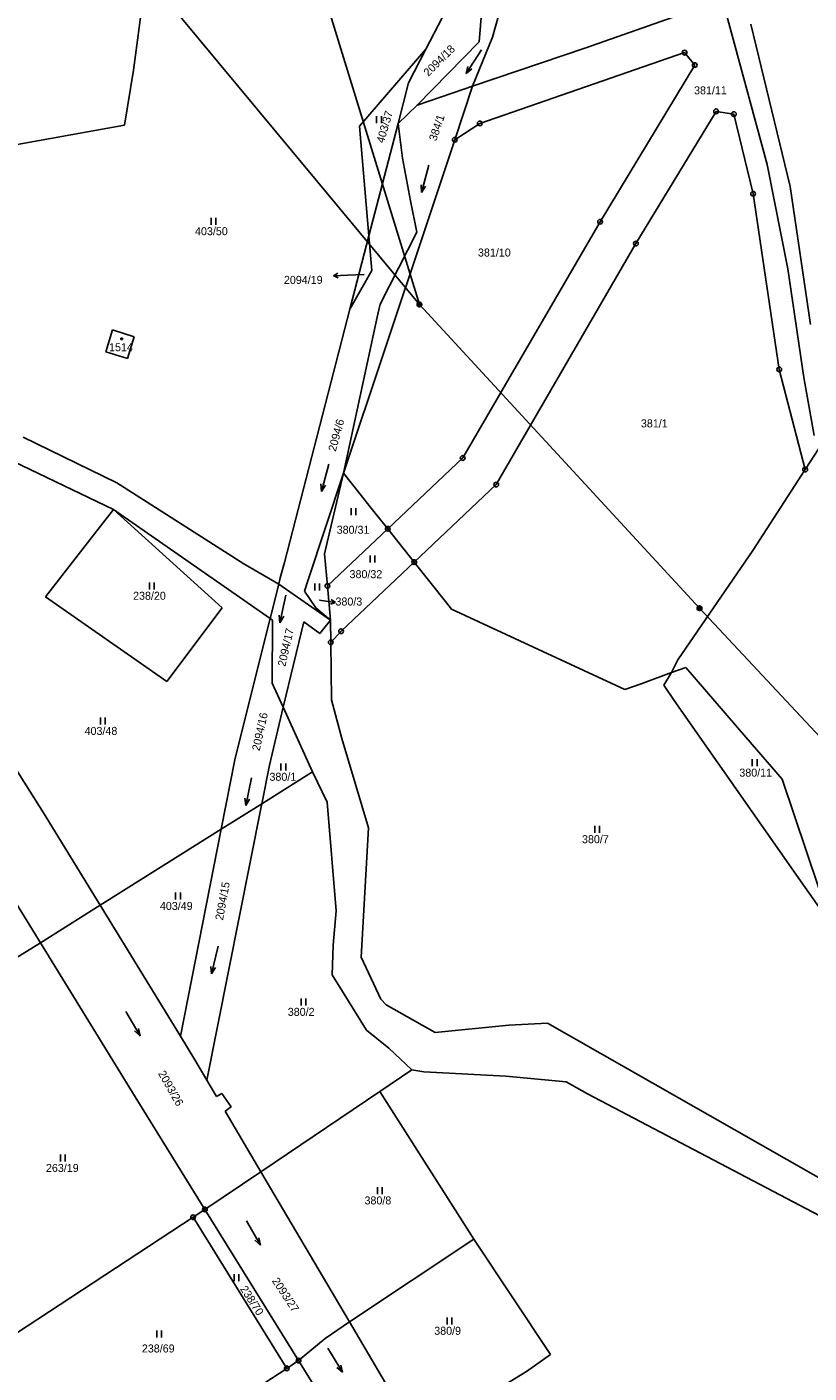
# Model space of a CAD drawing. Extents: x -795483 to -789093, y -1112258 to -1108741.
# Drawn here: x -791422.1 to -791256, y -1111421 to -1111135 of the extents above; entities that cross this region are included whole.
import ezdxf

# ---------------------------------------------------------------- set-up
doc = ezdxf.new("R2010")
doc.units = 0
for name, color, linetype in [('Komunikace', 7, 'Continuous'), ('Vrstva 1', 7, 'Continuous'), ('Vrstva 12', 7, 'Continuous'), ('Vrstva 14', 7, 'Continuous'), ('Vrstva 15', 7, 'Continuous'), ('Vrstva 16', 7, 'Continuous'), ('Vrstva 23', 7, 'Continuous'), ('Vrstva 25', 7, 'Continuous'), ('Vrstva 26', 7, 'Continuous'), ('Vrstva 28', 7, 'Continuous')]:
    doc.layers.add(name, color=color, linetype=linetype)

msp = doc.modelspace()

# ---------------------------------------------------------------- linework, layer by layer
at = {"layer": 'Komunikace'}
for p, q in [((-791350.48, -1111187.58), (-791354.05, -1111187.75)), ((-791359.99, -1111256.79), (-791359.58, -1111256.85))]:
    msp.add_line(p, q, dxfattribs=at)
at = {"layer": 'Vrstva 1'}
for p, q in [((-791326.07, -1111138.17), (-791324.04, -1111113.88)), ((-791399.5, -1111144.17), (-791397.48, -1111128.65)), ((-791303.42, -1111139.47), (-791274.38, -1111129.16)), ((-791274.38, -1111129.16), (-791264.93, -1111164.26)), ((-791321.94, -1111132.66), (-791323.21, -1111137.18)), ((-791333.93, -1111133.04), (-791337.37, -1111139.71)), ((-791268.4, -1111134.43), (-791260.02, -1111168.91)), ((-791326.07, -1111138.17), (-791339.22, -1111151.65)), ((-791323.21, -1111137.18), (-791327.47, -1111147.59)), ((-791351.47, -1111156.08), (-791337.37, -1111139.71)), ((-791337.37, -1111139.71), (-791341.07, -1111146.89)), ((-791327.47, -1111147.59), (-791303.42, -1111139.47)), ((-791325.94, -1111155.52), (-791282.44, -1111140.47)), ((-791282.44, -1111140.47), (-791280.29, -1111143.11)), ((-791401.41, -1111155.85), (-791399.5, -1111144.17)), ((-791280.29, -1111143.11), (-791300.38, -1111176.39)), ((-791341.07, -1111146.89), (-791343.31, -1111155.52)), ((-791329.35, -1111148.24), (-791339.22, -1111151.65)), ((-791327.47, -1111147.59), (-791331.26, -1111158.97)), ((-791327.47, -1111147.59), (-791329.35, -1111148.24)), ((-791339.22, -1111151.65), (-791343.31, -1111155.52)), ((-791343.31, -1111155.52), (-791349.49, -1111179.38)), ((-791342.38, -1111162.91), (-791343.31, -1111155.52)), ((-791331.26, -1111158.97), (-791325.94, -1111155.52)), ((-791292.78, -1111181.02), (-791275.74, -1111152.94)), ((-791275.74, -1111152.94), (-791271.97, -1111153.53)), ((-791271.97, -1111153.53), (-791267.88, -1111170.44)), ((-791448.95, -1111164.42), (-791401.41, -1111155.85)), ((-791349.49, -1111179.38), (-791351.47, -1111156.08)), ((-791337.36, -1111177.27), (-791331.26, -1111158.97)), ((-791340.69, -1111171.93), (-791342.38, -1111162.91)), ((-791264.93, -1111164.26), (-791260.5, -1111186.38)), ((-791260.02, -1111168.91), (-791255.67, -1111198.2)), ((-791339.35, -1111178.63), (-791340.69, -1111171.93)), ((-791267.88, -1111170.44), (-791262.33, -1111207.77)), ((-791337.36, -1111177.27), (-791354.86, -1111229.83)), ((-791300.38, -1111176.39), (-791329.58, -1111226.58)), ((-791349.49, -1111179.38), (-791353.53, -1111194.98)), ((-791348.86, -1111186.78), (-791349.49, -1111179.38)), ((-791339.35, -1111178.63), (-791347.11, -1111193.89)), ((-791322.44, -1111232.22), (-791292.78, -1111181.02)), ((-791353.53, -1111194.98), (-791348.86, -1111186.78)), ((-791260.5, -1111186.38), (-791257.08, -1111209.51)), ((-791353.53, -1111194.98), (-791367.46, -1111248.75)), ((-791347.71, -1111196.68), (-791347.11, -1111193.89)), ((-791354.86, -1111229.83), (-791347.71, -1111196.68)), ((-791405.4, -1111204.02), (-791403.94, -1111199.37)), ((-791403.94, -1111199.37), (-791399.34, -1111200.82)), ((-791399.34, -1111200.82), (-791400.81, -1111205.47)), ((-791400.81, -1111205.47), (-791405.4, -1111204.02)), ((-791262.33, -1111207.77), (-791256.83, -1111229.05)), ((-791257.08, -1111209.51), (-791254.89, -1111221.77)), ((-791422.96, -1111222.17), (-791403.02, -1111231.88)), ((-791429.62, -1111225.1), (-791403.76, -1111237.54)), ((-791329.58, -1111226.58), (-791345.49, -1111241.62)), ((-791253.93, -1111224.59), (-791256.83, -1111229.05)), ((-791362.47, -1111252.68), (-791354.86, -1111229.83)), ((-791358.92, -1111246.95), (-791354.86, -1111229.83)), ((-791354.86, -1111229.83), (-791351.62, -1111233.9)), ((-791267.97, -1111246.2), (-791256.83, -1111229.05)), ((-791403.02, -1111231.88), (-791376.07, -1111249.07)), ((-791339.87, -1111248.69), (-791322.44, -1111232.22)), ((-791348.7, -1111237.57), (-791351.62, -1111233.9)), ((-791403.76, -1111237.54), (-791408.28, -1111243.34)), ((-791380.66, -1111258.43), (-791403.76, -1111237.54)), ((-791403.76, -1111237.54), (-791370.48, -1111260.67)), ((-791348.7, -1111237.57), (-791345.49, -1111241.62)), ((-791408.28, -1111243.34), (-791418.17, -1111256.04)), ((-791345.49, -1111241.62), (-791358.32, -1111253.75)), ((-791345.49, -1111241.62), (-791339.87, -1111248.69)), ((-791453.88, -1111246.33), (-791418.6, -1111301.97)), ((-791358.92, -1111246.95), (-791358.32, -1111253.75)), ((-791267.97, -1111246.2), (-791283.86, -1111269.47)), ((-791376.07, -1111249.07), (-791368.65, -1111253.35)), ((-791368.32, -1111252.05), (-791367.46, -1111248.75)), ((-791355.42, -1111263.38), (-791339.87, -1111248.69)), ((-791333.22, -1111257.08), (-791339.87, -1111248.69)), ((-791368.65, -1111253.35), (-791368.32, -1111252.05)), ((-791363.2, -1111254.85), (-791362.47, -1111252.68)), ((-791370.48, -1111260.67), (-791368.65, -1111253.35)), ((-791368.65, -1111253.35), (-791357.67, -1111261.03)), ((-791360.8, -1111258.43), (-791363.2, -1111254.85)), ((-791357.67, -1111261.03), (-791358.32, -1111253.75)), ((-791418.17, -1111256.04), (-791392.39, -1111274.08)), ((-791392.39, -1111274.08), (-791380.66, -1111258.43)), ((-791357.67, -1111261.03), (-791360.8, -1111258.43)), ((-791331.93, -1111258.71), (-791333.22, -1111257.08)), ((-791375.78, -1111281.83), (-791370.48, -1111260.67)), ((-791370.48, -1111260.67), (-791369.94, -1111261.05)), ((-791370.02, -1111274.39), (-791369.94, -1111261.05)), ((-791367.7, -1111279.54), (-791363.35, -1111261.36)), ((-791363.35, -1111261.36), (-791359.95, -1111263.88)), ((-791359.95, -1111263.88), (-791357.67, -1111261.03)), ((-791357.67, -1111261.03), (-791357.6, -1111265.74)), ((-791295.1, -1111275.79), (-791331.93, -1111258.71)), ((-791357.6, -1111265.74), (-791355.42, -1111263.38)), ((-791357.42, -1111277.96), (-791357.6, -1111265.74)), ((-791283.86, -1111269.47), (-791285.22, -1111272.18)), ((-791285.22, -1111272.18), (-791291.64, -1111274.53)), ((-791285.22, -1111272.18), (-791286.82, -1111274.87)), ((-791282.21, -1111271.08), (-791285.22, -1111272.18)), ((-791282.21, -1111271.08), (-791269.4, -1111285.92)), ((-791367.7, -1111279.54), (-791370.02, -1111274.39)), ((-791291.64, -1111274.53), (-791295.1, -1111275.79)), ((-791284.64, -1111278.11), (-791286.82, -1111274.87)), ((-791357.42, -1111277.96), (-791355.27, -1111286.17)), ((-791284.64, -1111278.11), (-791256.81, -1111317.81)), ((-791370.63, -1111291.8), (-791367.7, -1111279.54)), ((-791361.51, -1111293.27), (-791367.7, -1111279.54)), ((-791378, -1111290.71), (-791375.78, -1111281.83)), ((-791355.27, -1111286.17), (-791349.55, -1111305.18)), ((-791269.4, -1111285.92), (-791261.7, -1111294.84)), ((-791380.9, -1111305.45), (-791378, -1111290.71)), ((-791372.27, -1111300.03), (-791370.63, -1111291.8)), ((-791372.27, -1111300.03), (-791361.51, -1111293.27)), ((-791361.51, -1111293.27), (-791358.37, -1111299.69)), ((-791261.7, -1111294.84), (-791251.41, -1111325.54)), ((-791383.91, -1111358.78), (-791372.39, -1111300.65)), ((-791380.9, -1111305.45), (-791372.27, -1111300.03)), ((-791372.39, -1111300.65), (-791372.27, -1111300.03)), ((-791358.37, -1111299.69), (-791356.44, -1111322.75)), ((-791406.58, -1111321.6), (-791418.6, -1111301.97)), ((-791406.58, -1111321.6), (-791380.9, -1111305.45)), ((-791389.54, -1111349.43), (-791380.9, -1111305.45)), ((-791351.14, -1111332.63), (-791349.55, -1111305.18)), ((-791428.96, -1111313.82), (-791419.28, -1111329.58)), ((-791256.81, -1111317.81), (-791251.41, -1111325.54)), ((-791419.28, -1111329.58), (-791406.58, -1111321.6)), ((-791389.54, -1111349.43), (-791406.58, -1111321.6)), ((-791356.44, -1111322.75), (-791357.08, -1111330.07)), ((-791438.46, -1111341.46), (-791419.28, -1111329.58)), ((-791419.28, -1111329.58), (-791399.16, -1111362.32)), ((-791357.08, -1111330.07), (-791357.33, -1111336.34)), ((-791351.14, -1111332.63), (-791346.99, -1111341.56)), ((-791357.33, -1111336.34), (-791350.01, -1111348.13)), ((-791346.99, -1111341.56), (-791345.85, -1111342.74)), ((-791345.85, -1111342.74), (-791335.44, -1111348.6)), ((-791335.44, -1111348.6), (-791319.76, -1111347.09)), ((-791311.54, -1111346.61), (-791319.76, -1111347.09)), ((-791240.86, -1111386.95), (-791311.54, -1111346.61)), ((-791389.54, -1111349.43), (-791386.5, -1111354.4)), ((-791350.01, -1111348.13), (-791345.27, -1111351.93)), ((-791345.27, -1111351.93), (-791340.41, -1111356.55)), ((-791383.91, -1111358.78), (-791386.5, -1111354.4)), ((-791340.41, -1111356.55), (-791347.16, -1111361.17)), ((-791340.41, -1111356.55), (-791337.86, -1111356.95)), ((-791337.86, -1111356.95), (-791320.38, -1111357.9)), ((-791320.38, -1111357.9), (-791307.61, -1111359.07)), ((-791381.88, -1111362.23), (-791383.91, -1111358.78)), ((-791347.16, -1111361.17), (-791372.45, -1111378.21)), ((-791327.21, -1111392.51), (-791347.16, -1111361.17)), ((-791307.61, -1111359.07), (-791303.09, -1111361.64)), ((-791384.34, -1111386.22), (-791399.16, -1111362.32)), ((-791381.88, -1111362.23), (-791380.77, -1111361.55)), ((-791378.77, -1111364.41), (-791380.77, -1111361.55)), ((-791303.09, -1111361.64), (-791233.75, -1111398.07)), ((-791380.06, -1111365.31), (-791378.77, -1111364.41)), ((-791372.45, -1111378.21), (-791380.06, -1111365.31)), ((-791372.45, -1111378.21), (-791384.34, -1111386.22)), ((-791353.64, -1111410.08), (-791372.45, -1111378.21)), ((-791386.85, -1111387.87), (-791384.34, -1111386.22)), ((-791384.34, -1111386.22), (-791364.44, -1111418.33)), ((-791426.8, -1111414.15), (-791386.85, -1111387.87)), ((-791366.95, -1111419.97), (-791386.85, -1111387.87)), ((-791353.64, -1111410.08), (-791327.21, -1111392.51)), ((-791327.21, -1111392.51), (-791310.95, -1111417.05)), ((-791358.8, -1111413.62), (-791353.64, -1111410.08)), ((-791353.64, -1111410.08), (-791338.74, -1111435.33)), ((-791364.44, -1111418.33), (-791358.8, -1111413.62)), ((-791364.44, -1111418.33), (-791366.95, -1111419.97)), ((-791349.61, -1111442.25), (-791364.44, -1111418.33)), ((-791310.95, -1111417.05), (-791316.05, -1111420.64)), ((-791366.95, -1111419.97), (-791406.97, -1111446.05)), ((-791316.05, -1111420.64), (-791324.24, -1111425.65))]:
    msp.add_line(p, q, dxfattribs=at)
at = {"layer": 'Vrstva 12'}
for p, q in [((-791338.78, -1111193.96), (-791359.28, -1111127.18)), ((-791390.3, -1111131.95), (-791338.78, -1111193.96)), ((-791338.78, -1111193.96), (-791279.28, -1111258.5)), ((-791279.28, -1111258.5), (-791219.02, -1111322.91))]:
    msp.add_line(p, q, dxfattribs=at)
at = {"layer": 'Vrstva 16'}
for p, q in [((-791357.05, -1111187.89), (-791356.07, -1111187.34)), ((-791354.05, -1111187.75), (-791357.05, -1111187.89)), ((-791357.05, -1111187.89), (-791356.02, -1111188.34)), ((-791359.58, -1111256.85), (-791356.61, -1111257.27)), ((-791356.61, -1111257.27), (-791357.67, -1111257.62)), ((-791356.61, -1111257.27), (-791357.53, -1111256.63))]:
    msp.add_line(p, q, dxfattribs=at)
at = {"layer": 'Vrstva 23'}
for p, q in [((-791325.6, -1111139.87), (-791328.83, -1111144.93)), ((-791328.83, -1111144.93), (-791328.45, -1111143.4)), ((-791328.83, -1111144.93), (-791327.6, -1111143.93)), ((-791347.85, -1111155.46), (-791347.85, -1111153.96)), ((-791346.85, -1111153.96), (-791346.85, -1111155.46)), ((-791336.75, -1111164.37), (-791338.35, -1111170.15)), ((-791338.35, -1111170.15), (-791338.43, -1111168.57)), ((-791338.35, -1111170.15), (-791337.47, -1111168.84)), ((-791383.03, -1111177.05), (-791383.03, -1111175.55)), ((-791382.03, -1111175.55), (-791382.03, -1111177.05)), ((-791357.98, -1111227.89), (-791359.6, -1111233.67)), ((-791359.6, -1111233.67), (-791359.68, -1111232.09)), ((-791359.6, -1111233.67), (-791358.71, -1111232.36)), ((-791353.3, -1111238.76), (-791353.3, -1111237.26)), ((-791352.3, -1111237.26), (-791352.3, -1111238.76)), ((-791349.22, -1111248.77), (-791349.22, -1111247.27)), ((-791348.22, -1111247.27), (-791348.22, -1111248.77)), ((-791396.1, -1111254.5), (-791396.1, -1111253)), ((-791395.1, -1111253), (-791395.1, -1111254.5)), ((-791367.17, -1111255.69), (-791368.39, -1111261.57)), ((-791360.96, -1111254.71), (-791360.96, -1111253.21)), ((-791359.96, -1111253.21), (-791359.96, -1111254.71)), ((-791368.39, -1111261.57), (-791368.57, -1111260)), ((-791368.39, -1111261.57), (-791367.59, -1111260.2)), ((-791406.53, -1111283.21), (-791406.53, -1111281.71)), ((-791405.53, -1111281.71), (-791405.53, -1111283.21)), ((-791368.17, -1111292.95), (-791368.17, -1111291.45)), ((-791367.17, -1111291.45), (-791367.17, -1111292.95)), ((-791268.06, -1111292.07), (-791268.06, -1111290.57)), ((-791267.06, -1111290.57), (-791267.06, -1111292.07)), ((-791374.43, -1111294.55), (-791375.67, -1111300.43)), ((-791375.67, -1111300.43), (-791375.85, -1111298.85)), ((-791375.67, -1111300.43), (-791374.87, -1111299.06)), ((-791301.51, -1111306.21), (-791301.51, -1111304.71)), ((-791300.51, -1111304.71), (-791300.51, -1111306.21)), ((-791390.55, -1111320.39), (-791390.55, -1111318.89)), ((-791389.55, -1111318.89), (-791389.55, -1111320.39)), ((-791381.51, -1111330.32), (-791382.91, -1111336.16)), ((-791382.91, -1111336.16), (-791383.05, -1111334.58)), ((-791382.91, -1111336.16), (-791382.07, -1111334.81)), ((-791363.91, -1111342.89), (-791363.91, -1111341.39)), ((-791362.91, -1111341.39), (-791362.91, -1111342.89)), ((-791401.14, -1111344.15), (-791398.1, -1111349.33)), ((-791398.1, -1111349.33), (-791399.29, -1111348.29)), ((-791398.1, -1111349.33), (-791398.43, -1111347.78)), ((-791415.03, -1111376.05), (-791415.03, -1111374.55)), ((-791414.03, -1111374.55), (-791414.03, -1111376.05)), ((-791347.65, -1111382.95), (-791347.65, -1111381.45)), ((-791346.65, -1111381.45), (-791346.65, -1111382.95)), ((-791375.53, -1111388.6), (-791372.55, -1111393.81)), ((-791372.55, -1111393.81), (-791373.73, -1111392.76)), ((-791372.55, -1111393.81), (-791372.86, -1111392.26)), ((-791378.13, -1111401.47), (-791378.13, -1111399.97)), ((-791377.13, -1111399.97), (-791377.13, -1111401.47)), ((-791332.87, -1111410.64), (-791332.87, -1111409.14)), ((-791331.87, -1111409.14), (-791331.87, -1111410.64)), ((-791394.54, -1111413.43), (-791394.54, -1111411.93)), ((-791393.54, -1111411.93), (-791393.54, -1111413.43)), ((-791358.19, -1111415.67), (-791355.1, -1111420.81)), ((-791355.1, -1111420.81), (-791356.31, -1111419.78)), ((-791355.1, -1111420.81), (-791355.45, -1111419.27))]:
    msp.add_line(p, q, dxfattribs=at)
at = {"layer": 'Vrstva 25'}
for p, q in [((-791402.17, -1111201.13), (-791401.87, -1111201.13)), ((-791402.17, -1111201.43), (-791402.17, -1111201.13)), ((-791401.87, -1111201.13), (-791401.87, -1111201.43)), ((-791401.87, -1111201.43), (-791402.17, -1111201.43))]:
    msp.add_line(p, q, dxfattribs=at)
at = {"layer": 'Vrstva 26'}
for p, q in [((-791339.28, -1111193.86), (-791339.18, -1111193.66)), ((-791339.28, -1111194.06), (-791339.28, -1111193.86)), ((-791339.18, -1111194.26), (-791339.28, -1111194.06)), ((-791339.18, -1111193.66), (-791339.08, -1111193.56)), ((-791339.08, -1111194.36), (-791339.18, -1111194.26)), ((-791339.08, -1111193.56), (-791338.88, -1111193.46)), ((-791339.08, -1111193.76), (-791339.08, -1111194.16)), ((-791339.08, -1111194.16), (-791338.88, -1111194.26)), ((-791338.88, -1111194.46), (-791339.08, -1111194.36)), ((-791338.88, -1111193.46), (-791338.68, -1111193.46)), ((-791338.88, -1111194.26), (-791338.88, -1111193.66)), ((-791338.88, -1111193.66), (-791338.68, -1111193.66)), ((-791338.68, -1111194.46), (-791338.88, -1111194.46)), ((-791338.68, -1111193.46), (-791338.48, -1111193.56)), ((-791338.68, -1111193.66), (-791338.68, -1111194.26)), ((-791338.68, -1111194.26), (-791338.48, -1111194.16)), ((-791338.48, -1111194.36), (-791338.68, -1111194.46)), ((-791338.48, -1111193.56), (-791338.38, -1111193.66)), ((-791338.48, -1111194.16), (-791338.48, -1111193.76)), ((-791338.38, -1111194.26), (-791338.48, -1111194.36)), ((-791338.38, -1111193.66), (-791338.28, -1111193.86)), ((-791338.28, -1111194.06), (-791338.38, -1111194.26)), ((-791338.28, -1111193.86), (-791338.28, -1111194.06)), ((-791279.78, -1111258.4), (-791279.68, -1111258.2)), ((-791279.78, -1111258.6), (-791279.78, -1111258.4)), ((-791279.68, -1111258.2), (-791279.58, -1111258.1)), ((-791279.58, -1111258.1), (-791279.38, -1111258)), ((-791279.58, -1111258.3), (-791279.58, -1111258.7)), ((-791279.38, -1111258), (-791279.18, -1111258)), ((-791279.38, -1111258.8), (-791279.38, -1111258.2)), ((-791279.38, -1111258.2), (-791279.18, -1111258.2)), ((-791279.18, -1111258), (-791278.98, -1111258.1)), ((-791279.18, -1111258.2), (-791279.18, -1111258.8)), ((-791278.98, -1111258.1), (-791278.88, -1111258.2)), ((-791278.98, -1111258.7), (-791278.98, -1111258.3)), ((-791278.88, -1111258.2), (-791278.78, -1111258.4)), ((-791278.78, -1111258.4), (-791278.78, -1111258.6)), ((-791279.68, -1111258.8), (-791279.78, -1111258.6)), ((-791279.58, -1111258.9), (-791279.68, -1111258.8)), ((-791279.58, -1111258.7), (-791279.38, -1111258.8)), ((-791279.38, -1111259), (-791279.58, -1111258.9)), ((-791279.18, -1111259), (-791279.38, -1111259)), ((-791279.18, -1111258.8), (-791278.98, -1111258.7)), ((-791278.98, -1111258.9), (-791279.18, -1111259)), ((-791278.88, -1111258.8), (-791278.98, -1111258.9)), ((-791278.78, -1111258.6), (-791278.88, -1111258.8))]:
    msp.add_line(p, q, dxfattribs=at)
at = {"layer": 'Vrstva 28'}
for centre, radius in [((-791282.44, -1111140.47), 0.5), ((-791282.44, -1111140.47), 0.01), ((-791280.29, -1111143.11), 0.5), ((-791280.29, -1111143.11), 0.01), ((-791275.74, -1111152.94), 0.5), ((-791325.94, -1111155.52), 0.5), ((-791325.94, -1111155.52), 0.01), ((-791275.74, -1111152.94), 0.01), ((-791271.97, -1111153.53), 0.5), ((-791271.97, -1111153.53), 0.01), ((-791331.26, -1111158.97), 0.5), ((-791331.26, -1111158.97), 0.01), ((-791267.88, -1111170.44), 0.5), ((-791267.88, -1111170.44), 0.01), ((-791300.38, -1111176.39), 0.5), ((-791300.38, -1111176.39), 0.01), ((-791292.78, -1111181.02), 0.5), ((-791292.78, -1111181.02), 0.01), ((-791262.33, -1111207.77), 0.5), ((-791262.33, -1111207.77), 0.01), ((-791329.58, -1111226.58), 0.5), ((-791329.58, -1111226.58), 0.01), ((-791256.83, -1111229.05), 0.5), ((-791256.83, -1111229.05), 0.01), ((-791322.44, -1111232.22), 0.5), ((-791322.44, -1111232.22), 0.01), ((-791345.49, -1111241.62), 0.5), ((-791345.49, -1111241.62), 0.01), ((-791339.87, -1111248.69), 0.5), ((-791339.87, -1111248.69), 0.01), ((-791358.32, -1111253.75), 0.5), ((-791358.32, -1111253.75), 0.01), ((-791355.42, -1111263.38), 0.5), ((-791355.42, -1111263.38), 0.01), ((-791357.6, -1111265.74), 0.5), ((-791357.6, -1111265.74), 0.01), ((-791384.34, -1111386.22), 0.5), ((-791384.34, -1111386.22), 0.01), ((-791386.85, -1111387.87), 0.5), ((-791386.85, -1111387.87), 0.01), ((-791364.44, -1111418.33), 0.5), ((-791364.44, -1111418.33), 0.01), ((-791366.95, -1111419.97), 0.5), ((-791366.95, -1111419.97), 0.01)]:
    msp.add_circle(centre, radius, dxfattribs=at)

# ---------------------------------------------------------------- texts
at = {"layer": 'Vrstva 14'}
for s, rotation, p in [('2094/18', 44.7268, (-791336.89, -1111145.64)), ('403/37', 73.8158, (-791346.32, -1111159.8)), ('384/1', 71.3447, (-791335.19, -1111159.37)), ('2094/6', 74.7137, (-791356.54, -1111225.31)), ('2094/17', 77.1318, (-791367.26, -1111270.99)), ('2094/16', 77.671, (-791372.71, -1111288.9)), ('2094/15', 79.63, (-791380.5, -1111324.89)), ('2093/26', 299.6491, (-791394.34, -1111357.32)), ('2093/27', 303.4899, (-791370.17, -1111401.39)), ('238/70', 302.9933, (-791376.94, -1111403.09))]:
    msp.add_text(s, height=1.7, rotation=rotation, dxfattribs=at).set_placement(p)
for s, height, p in [('381/11', 1.7, (-791280.43, -1111149.33)), ('403/50', 1.7, (-791386.43, -1111179.25)), ('381/10', 1.7, (-791326.33, -1111183.78)), ('2094/19', 0.1, (-791350.48, -1111187.58)), ('381/1', 1.7, (-791291.72, -1111220.08)), ('380/31', 1.7, (-791356.34, -1111242.67)), ('380/32', 1.7, (-791353.61, -1111252.11)), ('238/20', 1.7, (-791399.59, -1111256.7)), ('380/3', 0.1, (-791360.2, -1111256.79)), ('403/48', 1.7, (-791409.89, -1111285.41)), ('380/11', 1.7, (-791270.81, -1111294.27)), ('380/1', 1.7, (-791370.62, -1111295.15)), ('380/7', 1.7, (-791304.23, -1111308.41)), ('403/49', 1.7, (-791393.89, -1111322.59)), ('380/2', 1.7, (-791366.73, -1111345.09)), ('263/19', 1.7, (-791418.1, -1111378.25)), ('380/8', 1.7, (-791350.43, -1111385.15)), ('380/9', 1.7, (-791335.62, -1111412.84)), ('238/69', 1.7, (-791397.72, -1111416.6))]:
    msp.add_text(s, height=height, dxfattribs=at).set_placement(p)
at = {"layer": 'Vrstva 15'}
msp.add_text('1514', height=1.7, dxfattribs=at).set_placement((-791404.69, -1111203.89))
at = {"layer": 'Vrstva 16'}
for s, p in [('2094/19', (-791367.55, -1111189.59)), ('380/3', (-791356.6, -1111257.92))]:
    msp.add_text(s, height=1.7, dxfattribs=at).set_placement(p)

doc.saveas('drawing.dxf')
